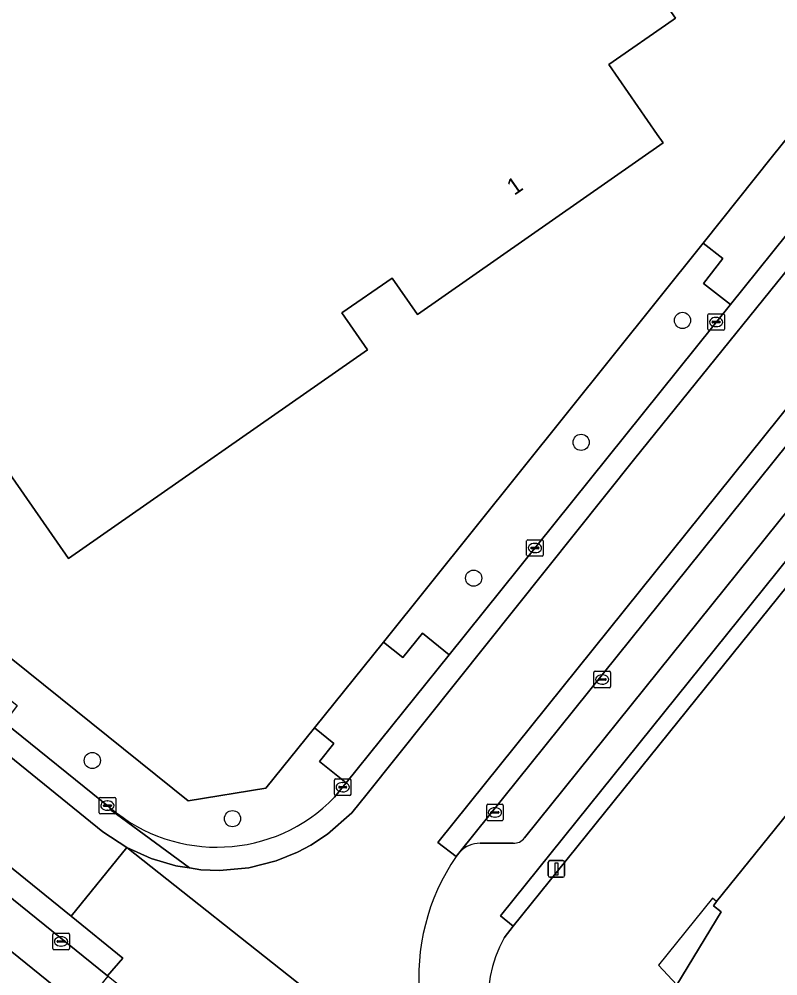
# Model space of a CAD drawing. Extents: x 156702 to 158052, y 387630 to 388992.
# Drawn here: x 157335.4 to 157381.2, y 388068.3 to 388126 of the extents above; entities that cross this region are included whole.
import ezdxf

# ---------------------------------------------------------------- set-up
doc = ezdxf.new("R2010")
doc.units = 0
for name, color, linetype in [('IMGEO_Berm_groen', 7, 'Continuous'), ('IMGEO_Boom', 7, 'Continuous'), ('IMGEO_Erf', 7, 'Continuous'), ('IMGEO_Groenvoorziening', 7, 'Continuous'), ('IMGEO_Hek', 7, 'Continuous'), ('IMGEO_Kolk', 7, 'Continuous'), ('IMGEO_Lichtmast', 7, 'Continuous'), ('IMGEO_Pand', 7, 'Continuous'), ('IMGEO_Pand_nummerreeks', 7, 'Continuous'), ('IMGEO_Pand_overbouw', 7, 'Continuous'), ('IMGEO_Parkeervlak_open', 7, 'Continuous'), ('IMGEO_Rijbaan_lokaal_gesloten', 7, 'Continuous'), ('IMGEO_Rijbaan_lokaal_open', 7, 'Continuous'), ('IMGEO_Voetpad_open', 7, 'Continuous')]:
    doc.layers.add(name, color=color, linetype=linetype)

msp = doc.modelspace()

# ---------------------------------------------------------------- linework, layer by layer
at = {"layer": 'IMGEO_Berm_groen'}
msp.add_lwpolyline([(157378.344, 388108.801), (157376.726, 388110.062), (157377.891, 388111.57), (157376.693, 388112.497), (157357.392, 388088.42), (157358.573, 388087.49), (157359.755, 388088.963), (157361.36, 388087.666)], close=True, dxfattribs=at)
for points in [[(157354.447, 388079.064), (157355.149, 388079.934), (157353.539, 388081.22), (157354.397, 388082.311), (157353.239, 388083.252), (157350.282, 388079.607), (157345.604, 388078.857), (157309.704, 388107.668)], [(157316.025, 388098.512), (157328.627, 388088.335), (157329.374, 388089.304), (157335.28, 388084.592), (157334.514, 388083.582), (157340.899, 388078.426)]]:
    msp.add_lwpolyline(points, dxfattribs=at)
msp.add_arc((157347.333, 388085.955), 9.904, 229.48202, 315.91032, dxfattribs=at)
at = {"layer": 'IMGEO_Boom'}
for centre in [(157375.454, 388107.837), (157369.333, 388100.48), (157362.84, 388092.285), (157339.812, 388081.28), (157348.276, 388077.77)]:
    msp.add_circle(centre, 0.489, dxfattribs=at)
at = {"layer": 'IMGEO_Erf'}
for points in [[(157304.594, 388111.931), (157309.704, 388107.668), (157345.604, 388078.857), (157350.282, 388079.607), (157353.239, 388083.252), (157357.392, 388088.42), (157376.693, 388112.497), (157380.893, 388117.749), (157391.144, 388130.462), (157404.098, 388146.633), (157406.558, 388149.7), (157418.329, 388164.322), (157428.032, 388175.523), (157430.343, 388177.94), (157441.633, 388189.119), (157442.935, 388190.379), (157453.889, 388200.705), (157463.105, 388209.35), (157478.926, 388224.264), (157484.402, 388229.388), (157504.128, 388247.959), (157518.512, 388268.247), (157504.449, 388292.394)], [(157493.249, 388214.823), (157491.107, 388212.731), (157491.239, 388212.61), (157490.267, 388211.711), (157481.015, 388202.978), (157480.83, 388203.161), (157468.85, 388191.959), (157469.027, 388191.734), (157464.53, 388187.517), (157456.336, 388179.654), (157444.998, 388168.465), (157439.451, 388162.839), (157439.425, 388162.812), (157437.029, 388160.17), (157418.031, 388136.851), (157411.021, 388128.098), (157365.224, 388071.291), (157364.694, 388070.576)], [(157375.12, 388067.746), (157377.791, 388072.155), (157377.317, 388072.514), (157377.518, 388072.763), (157393.215, 388092.187), (157408.126, 388110.639), (157409.261, 388112.047), (157409.462, 388112.296), (157409.944, 388111.907), (157413.497, 388115.283), (157415.217, 388117.029), (157415.445, 388117.256), (157419.983, 388112.463), (157419.758, 388112.25), (157419.62, 388112.395), (157417.986, 388110.394), (157419.843, 388108.498), (157420.585, 388107.61), (157424.453, 388103.559), (157425.389, 388102.574), (157427.433, 388104.491), (157431.942, 388099.714), (157436.485, 388094.9)]]:
    msp.add_lwpolyline(points, dxfattribs=at)
msp.add_lwpolyline([(157351.143, 388160.273), (157367.369, 388137.046), (157375.029, 388126.081), (157374.884, 388125.98), (157371, 388123.278), (157373.931, 388119.066), (157374.291, 388118.549), (157359.447, 388108.199), (157357.92, 388110.389), (157354.876, 388108.287), (157356.429, 388106.057), (157338.379, 388093.469), (157327.058, 388109.73), (157327.201, 388109.843), (157311.351, 388132.544), (157338.607, 388151.537)], close=True, dxfattribs=at)
msp.add_arc((157370.722, 388067.056), 6.981, 149.71613, 230.3307, dxfattribs=at)
at = {"layer": 'IMGEO_Groenvoorziening'}
msp.add_lwpolyline([(157365.224, 388071.291), (157411.021, 388128.098), (157410.172, 388128.763), (157409.295, 388127.628), (157364.459, 388071.912)], close=True, dxfattribs=at)
at = {"layer": 'IMGEO_Hek'}
for points in [[(157380.893, 388117.749), (157376.693, 388112.497)], [(157376.693, 388112.497), (157357.392, 388088.42)], [(157304.594, 388111.931), (157309.704, 388107.668), (157345.604, 388078.857), (157350.282, 388079.607), (157353.239, 388083.252)]]:
    msp.add_lwpolyline(points, dxfattribs=at)
at = {"layer": 'IMGEO_Kolk'}
for p, q in [((157376.983, 388107.315), (157376.983, 388108.167)), ((157377.058, 388108.241), (157377.91, 388108.241)), ((157377.984, 388108.167), (157377.984, 388107.315)), ((157377.242, 388107.735), (157377.242, 388107.747)), ((157377.68, 388107.698), (157377.282, 388107.698)), ((157377.285, 388107.784), (157377.683, 388107.784)), ((157377.471, 388108.021), (157377.496, 388108.021)), ((157377.726, 388107.747), (157377.726, 388107.735)), ((157377.91, 388107.241), (157377.058, 388107.241)), ((157377.494, 388107.461), (157377.469, 388107.461)), ((157366.043, 388093.679), (157366.043, 388094.531)), ((157366.118, 388094.605), (157366.97, 388094.605)), ((157366.531, 388094.385), (157366.556, 388094.385)), ((157367.044, 388094.531), (157367.044, 388093.679)), ((157366.302, 388094.099), (157366.302, 388094.111)), ((157366.74, 388094.062), (157366.342, 388094.062)), ((157366.345, 388094.148), (157366.743, 388094.148)), ((157366.554, 388093.825), (157366.529, 388093.825)), ((157366.786, 388094.111), (157366.786, 388094.099)), ((157366.97, 388093.605), (157366.118, 388093.605)), ((157370.101, 388085.741), (157370.101, 388086.593)), ((157370.176, 388086.667), (157371.028, 388086.667)), ((157370.589, 388086.447), (157370.614, 388086.447)), ((157371.102, 388086.593), (157371.102, 388085.741)), ((157371.028, 388085.667), (157370.176, 388085.667)), ((157370.36, 388086.161), (157370.36, 388086.173)), ((157370.798, 388086.124), (157370.4, 388086.124)), ((157370.403, 388086.21), (157370.801, 388086.21)), ((157370.612, 388085.887), (157370.587, 388085.887)), ((157370.844, 388086.173), (157370.844, 388086.161)), ((157354.433, 388079.245), (157354.433, 388080.097)), ((157354.508, 388080.171), (157355.36, 388080.171)), ((157354.921, 388079.951), (157354.946, 388079.951)), ((157355.434, 388080.097), (157355.434, 388079.245)), ((157354.692, 388079.665), (157354.692, 388079.677)), ((157355.13, 388079.628), (157354.732, 388079.628)), ((157354.735, 388079.714), (157355.133, 388079.714)), ((157354.944, 388079.391), (157354.919, 388079.391)), ((157355.176, 388079.677), (157355.176, 388079.665)), ((157340.223, 388078.132), (157340.223, 388078.984)), ((157340.298, 388079.058), (157341.15, 388079.058)), ((157340.711, 388078.838), (157340.736, 388078.838)), ((157341.224, 388078.984), (157341.224, 388078.132)), ((157355.36, 388079.171), (157354.508, 388079.171)), ((157340.482, 388078.552), (157340.482, 388078.564)), ((157340.92, 388078.515), (157340.522, 388078.515)), ((157340.525, 388078.601), (157340.923, 388078.601)), ((157340.734, 388078.278), (157340.709, 388078.278)), ((157340.966, 388078.564), (157340.966, 388078.552)), ((157363.628, 388077.723), (157363.628, 388078.575)), ((157363.703, 388078.649), (157364.555, 388078.649)), ((157363.887, 388078.143), (157363.887, 388078.155)), ((157363.93, 388078.192), (157364.328, 388078.192)), ((157364.116, 388078.429), (157364.141, 388078.429)), ((157364.371, 388078.155), (157364.371, 388078.143)), ((157364.629, 388078.575), (157364.629, 388077.723)), ((157341.15, 388078.058), (157340.298, 388078.058)), ((157364.555, 388077.649), (157363.703, 388077.649)), ((157364.325, 388078.106), (157363.927, 388078.106)), ((157364.139, 388077.869), (157364.114, 388077.869)), ((157337.424, 388069.939), (157337.424, 388070.791)), ((157337.499, 388070.865), (157338.351, 388070.865)), ((157337.912, 388070.645), (157337.937, 388070.645)), ((157338.425, 388070.791), (157338.425, 388069.939)), ((157337.683, 388070.359), (157337.683, 388070.371)), ((157338.121, 388070.322), (157337.723, 388070.322)), ((157337.726, 388070.408), (157338.124, 388070.408)), ((157337.935, 388070.085), (157337.91, 388070.085)), ((157338.167, 388070.371), (157338.167, 388070.359)), ((157338.351, 388069.865), (157337.499, 388069.865))]:
    msp.add_line(p, q, dxfattribs=at)
for points in [[(157376.983, 388107.315), (157376.983, 388108.167)], [(157377.058, 388108.241), (157377.91, 388108.241)], [(157377.984, 388108.167), (157377.984, 388107.315)], [(157377.91, 388107.241), (157377.058, 388107.241)], [(157366.043, 388093.679), (157366.043, 388094.531)], [(157366.118, 388094.605), (157366.97, 388094.605)], [(157367.044, 388094.531), (157367.044, 388093.679)], [(157366.97, 388093.605), (157366.118, 388093.605)], [(157370.101, 388085.741), (157370.101, 388086.593)], [(157370.176, 388086.667), (157371.028, 388086.667)], [(157371.102, 388086.593), (157371.102, 388085.741)], [(157371.028, 388085.667), (157370.176, 388085.667)], [(157354.433, 388079.245), (157354.433, 388080.097)], [(157354.508, 388080.171), (157355.36, 388080.171)], [(157355.434, 388080.097), (157355.434, 388079.245)], [(157340.223, 388078.132), (157340.223, 388078.984)], [(157340.298, 388079.058), (157341.15, 388079.058)], [(157341.224, 388078.984), (157341.224, 388078.132)], [(157355.36, 388079.171), (157354.508, 388079.171)], [(157363.628, 388077.723), (157363.628, 388078.575)], [(157363.703, 388078.649), (157364.555, 388078.649)], [(157364.629, 388078.575), (157364.629, 388077.723)], [(157341.15, 388078.058), (157340.298, 388078.058)], [(157364.555, 388077.649), (157363.703, 388077.649)], [(157337.424, 388069.939), (157337.424, 388070.791)], [(157337.499, 388070.865), (157338.351, 388070.865)], [(157338.425, 388070.791), (157338.425, 388069.939)], [(157338.351, 388069.865), (157337.499, 388069.865)]]:
    msp.add_lwpolyline(points, dxfattribs=at)
for centre, radius, start, end in [((157377.06, 388108.165), 0.0765, 91.55205, 178.44795), ((157377.06, 388108.165), 0.0765, 91.55205, 178.44795), ((157377.908, 388108.165), 0.0765, 1.55205, 88.44795), ((157377.908, 388108.165), 0.0765, 1.55205, 88.44795), ((157377.282, 388107.744), 0.0403, 85.87752, 175.75265), ((157377.279, 388107.734), 0.0366, 178.93798, 274.71019), ((157377.683, 388107.741), 0.043, 264.86636, 352.45326), ((157377.687, 388107.746), 0.0386, 1.73085, 96.63898), ((157377.06, 388107.317), 0.0765, 181.55205, 268.44795), ((157377.06, 388107.317), 0.0765, 181.55205, 268.44795), ((157377.908, 388107.317), 0.0765, 271.55205, 358.44795), ((157377.908, 388107.317), 0.0765, 271.55205, 358.44795), ((157366.12, 388094.529), 0.0765, 91.55205, 178.44795), ((157366.12, 388094.529), 0.0765, 91.55205, 178.44795), ((157366.968, 388094.529), 0.0765, 1.55205, 88.44795), ((157366.968, 388094.529), 0.0765, 1.55205, 88.44795), ((157366.342, 388094.108), 0.0403, 85.87752, 175.75265), ((157366.339, 388094.098), 0.0366, 178.93798, 274.71019), ((157366.743, 388094.105), 0.043, 264.86636, 352.45326), ((157366.747, 388094.11), 0.0386, 1.73085, 96.63898), ((157366.12, 388093.681), 0.0765, 181.55205, 268.44795), ((157366.12, 388093.681), 0.0765, 181.55205, 268.44795), ((157366.968, 388093.681), 0.0765, 271.55205, 358.44795), ((157366.968, 388093.681), 0.0765, 271.55205, 358.44795), ((157370.178, 388086.591), 0.0765, 91.55205, 178.44795), ((157370.178, 388086.591), 0.0765, 91.55205, 178.44795), ((157371.026, 388086.591), 0.0765, 1.55205, 88.44795), ((157371.026, 388086.591), 0.0765, 1.55205, 88.44795), ((157370.178, 388085.743), 0.0765, 181.55205, 268.44795), ((157370.178, 388085.743), 0.0765, 181.55205, 268.44795), ((157370.4, 388086.17), 0.0403, 85.87752, 175.75265), ((157370.397, 388086.16), 0.0366, 178.93798, 274.71019), ((157370.801, 388086.167), 0.043, 264.86636, 352.45326), ((157370.805, 388086.172), 0.0386, 1.73085, 96.63898), ((157371.026, 388085.743), 0.0765, 271.55205, 358.44795), ((157371.026, 388085.743), 0.0765, 271.55205, 358.44795), ((157354.51, 388080.095), 0.0765, 91.55205, 178.44795), ((157354.51, 388080.095), 0.0765, 91.55205, 178.44795), ((157355.358, 388080.095), 0.0765, 1.55205, 88.44795), ((157355.358, 388080.095), 0.0765, 1.55205, 88.44795), ((157354.732, 388079.674), 0.0403, 85.87752, 175.75265), ((157354.729, 388079.664), 0.0366, 178.93798, 274.71019), ((157355.133, 388079.671), 0.043, 264.86636, 352.45326), ((157355.137, 388079.676), 0.0386, 1.73085, 96.63898), ((157340.3, 388078.982), 0.0765, 91.55205, 178.44795), ((157340.3, 388078.982), 0.0765, 91.55205, 178.44795), ((157341.148, 388078.982), 0.0765, 1.55205, 88.44795), ((157341.148, 388078.982), 0.0765, 1.55205, 88.44795), ((157354.51, 388079.247), 0.0765, 181.55205, 268.44795), ((157354.51, 388079.247), 0.0765, 181.55205, 268.44795), ((157355.358, 388079.247), 0.0765, 271.55205, 358.44795), ((157355.358, 388079.247), 0.0765, 271.55205, 358.44795), ((157340.522, 388078.561), 0.0403, 85.87752, 175.75265), ((157340.519, 388078.551), 0.0366, 178.93798, 274.71019), ((157340.923, 388078.558), 0.043, 264.86636, 352.45326), ((157340.927, 388078.563), 0.0386, 1.73085, 96.63898), ((157363.705, 388078.573), 0.0765, 91.55205, 178.44795), ((157363.705, 388078.573), 0.0765, 91.55205, 178.44795), ((157363.927, 388078.152), 0.0403, 85.87752, 175.75265), ((157364.332, 388078.154), 0.0386, 1.73085, 96.63898), ((157364.553, 388078.573), 0.0765, 1.55205, 88.44795), ((157364.553, 388078.573), 0.0765, 1.55205, 88.44795), ((157340.3, 388078.134), 0.0765, 181.55205, 268.44795), ((157340.3, 388078.134), 0.0765, 181.55205, 268.44795), ((157341.148, 388078.134), 0.0765, 271.55205, 358.44795), ((157341.148, 388078.134), 0.0765, 271.55205, 358.44795), ((157363.705, 388077.725), 0.0765, 181.55205, 268.44795), ((157363.705, 388077.725), 0.0765, 181.55205, 268.44795), ((157363.924, 388078.142), 0.0366, 178.93798, 274.71019), ((157364.328, 388078.149), 0.043, 264.86636, 352.45326), ((157364.553, 388077.725), 0.0765, 271.55205, 358.44795), ((157364.553, 388077.725), 0.0765, 271.55205, 358.44795), ((157337.501, 388070.789), 0.0765, 91.55205, 178.44795), ((157337.501, 388070.789), 0.0765, 91.55205, 178.44795), ((157338.349, 388070.789), 0.0765, 1.55205, 88.44795), ((157338.349, 388070.789), 0.0765, 1.55205, 88.44795), ((157337.723, 388070.368), 0.0403, 85.87752, 175.75265), ((157337.72, 388070.358), 0.0366, 178.93798, 274.71019), ((157338.124, 388070.365), 0.043, 264.86636, 352.45326), ((157338.128, 388070.37), 0.0386, 1.73085, 96.63898), ((157337.501, 388069.941), 0.0765, 181.55205, 268.44795), ((157337.501, 388069.941), 0.0765, 181.55205, 268.44795), ((157338.349, 388069.941), 0.0765, 271.55205, 358.44795), ((157338.349, 388069.941), 0.0765, 271.55205, 358.44795)]:
    msp.add_arc(centre, radius, start, end, dxfattribs=at)
for centre, major_axis, ratio, start_param, end_param in [((157377.47, 388107.741), (-0.387, 0.002), 0.722429, 4.712389, 7.853982), ((157377.495, 388107.741), (-0.39, 0.002), 0.717154, 1.570796, 4.712389), ((157366.53, 388094.105), (-0.387, 0.002), 0.722429, 4.712389, 7.853982), ((157366.555, 388094.105), (-0.39, 0.002), 0.717154, 1.570796, 4.712389), ((157370.588, 388086.167), (-0.387, 0.002), 0.722429, 4.712389, 7.853982), ((157370.613, 388086.167), (-0.39, 0.002), 0.717154, 1.570796, 4.712389), ((157354.92, 388079.671), (-0.387, 0.002), 0.722429, 4.712389, 7.853982), ((157354.945, 388079.671), (-0.39, 0.002), 0.717154, 1.570796, 4.712389), ((157340.71, 388078.558), (-0.387, 0.002), 0.722429, 4.712389, 7.853982), ((157340.735, 388078.558), (-0.39, 0.002), 0.717154, 1.570796, 4.712389), ((157364.115, 388078.149), (-0.387, 0.002), 0.722429, 4.712389, 7.853982), ((157364.14, 388078.149), (-0.39, 0.002), 0.717154, 1.570796, 4.712389), ((157337.911, 388070.365), (-0.387, 0.002), 0.722429, 4.712389, 7.853982), ((157337.936, 388070.365), (-0.39, 0.002), 0.717154, 1.570796, 4.712389)]:
    msp.add_ellipse(centre, major_axis=major_axis, ratio=ratio, start_param=start_param, end_param=end_param, dxfattribs=at)
at = {"layer": 'IMGEO_Lichtmast'}
for p, q in [((157367.346, 388074.338), (157367.346, 388075.138)), ((157367.346, 388075.138), (157367.346, 388074.338)), ((157367.446, 388075.238), (157368.236, 388075.238)), ((157368.236, 388075.238), (157367.446, 388075.238)), ((157368.336, 388075.138), (157368.336, 388074.338)), ((157368.336, 388074.338), (157368.336, 388075.138)), ((157368.236, 388074.238), (157367.446, 388074.238)), ((157367.446, 388074.238), (157368.236, 388074.238))]:
    msp.add_line(p, q, dxfattribs=at)
msp.add_lwpolyline([(157367.766, 388075.113), (157367.916, 388075.113), (157367.916, 388074.363), (157367.766, 388074.363), (157367.766, 388075.113)], dxfattribs=at)
for centre, start, end in [((157367.446, 388075.138), 90, 180), ((157367.446, 388075.138), 90, 180), ((157368.236, 388075.138), 0, 90), ((157368.236, 388075.138), 360, 90), ((157367.446, 388074.338), 180, 270), ((157367.446, 388074.338), 180, 270), ((157368.236, 388074.338), 270, 0), ((157368.236, 388074.338), 270, 0)]:
    msp.add_arc(centre, 0.1, start, end, dxfattribs=at)
at = {"layer": 'IMGEO_Pand'}
for points in [[(157371, 388123.278), (157374.884, 388125.98), (157375.029, 388126.081), (157367.369, 388137.046), (157351.143, 388160.273), (157338.607, 388151.537), (157311.351, 388132.544), (157327.201, 388109.843), (157327.058, 388109.73), (157338.379, 388093.469), (157356.429, 388106.057), (157354.876, 388108.287), (157357.92, 388110.389), (157359.447, 388108.199), (157374.291, 388118.549), (157373.931, 388119.066)], [(157401.351, 388085.55), (157393.215, 388092.187), (157377.518, 388072.763), (157377.317, 388072.514), (157377.791, 388072.155), (157375.12, 388067.746), (157373.801, 388065.569), (157373.516, 388065.423), (157378.044, 388060.636), (157378.275, 388060.85), (157378.097, 388061.046), (157379.662, 388063.087), (157381.537, 388061.074), (157399.778, 388083.607), (157400.684, 388084.726)]]:
    msp.add_lwpolyline(points, close=True, dxfattribs=at)
at = {"layer": 'IMGEO_Pand_overbouw'}
msp.add_lwpolyline([(157377.518, 388072.763), (157377.272, 388072.972), (157374.006, 388068.927), (157375.12, 388067.746), (157377.791, 388072.155), (157377.317, 388072.514)], close=True, dxfattribs=at)
at = {"layer": 'IMGEO_Parkeervlak_open'}
for points in [[(157407.869, 388128.768), (157405.894, 388130.347), (157362.018, 388075.78)], [(157365.917, 388076.612), (157407.869, 388128.768)], [(157363.228, 388076.287), (157365.218, 388076.297)]]:
    msp.add_lwpolyline(points, dxfattribs=at)
for centre, radius, start, end in [((157365.291, 388077.069), 0.775, 264.63114, 323.88569), ((157363.235, 388074.573), 1.714, 90.23714, 135.23103)]:
    msp.add_arc(centre, radius, start, end, dxfattribs=at)
at = {"layer": 'IMGEO_Rijbaan_lokaal_gesloten'}
for points in [[(157159.256, 388297.816), (157160.307, 388298.772), (157166.301, 388290.299), (157236.347, 388190.018), (157288.771, 388114.767), (157287.657, 388113.917), (157306.474, 388095.88), (157307.404, 388097.063), (157338.534, 388071.878), (157341.899, 388076.038), (157340.456, 388076.982), (157309.901, 388101.717)], [(157372.577, 388099.512), (157397.82, 388130.747), (157409.349, 388145.114), (157418.054, 388155.99), (157428.31, 388168.424), (157433.998, 388174.762), (157442.081, 388182.987), (157451.011, 388191.483), (157458.709, 388198.857), (157466.448, 388206.061), (157472.586, 388211.776), (157482.524, 388221.195), (157508.983, 388245.953), (157519.658, 388255.905)], [(157441.766, 388173.495), (157445.382, 388177.09), (157464.923, 388195.684), (157464.997, 388195.754), (157486.423, 388215.896), (157487.488, 388216.939), (157486.56, 388217.944), (157464.339, 388197.057), (157445.628, 388179.257), (157440.454, 388174.149), (157437.14, 388170.615), (157432.703, 388165.68), (157427.336, 388159.248), (157360.67, 388076.338), (157361.788, 388075.495), (157362.018, 388075.78), (157405.894, 388130.347)], [(157361.788, 388075.495), (157360.67, 388076.338), (157427.336, 388159.248), (157432.703, 388165.68), (157437.14, 388170.615), (157440.454, 388174.149), (157445.628, 388179.257), (157464.339, 388197.057), (157486.56, 388217.944)], [(157425.667, 388167.547), (157419.954, 388160.554), (157409.376, 388147.415), (157406.909, 388144.334), (157395.189, 388129.737), (157378.344, 388108.801), (157361.36, 388087.666), (157355.149, 388079.934), (157354.447, 388079.064)], [(157397.82, 388130.747), (157372.577, 388099.512), (157356.41, 388079.268), (157355.48, 388078.115), (157354.015, 388076.833), (157353.016, 388076.181), (157352.205, 388075.752), (157350.909, 388075.228), (157349.26, 388074.812), (157347.485, 388074.649), (157346.364, 388074.69), (157345.672, 388074.796), (157344.981, 388074.902), (157344.863, 388074.92), (157343.374, 388075.363), (157341.899, 388076.038), (157363.348, 388059.054)], [(157284.128, 388130.537), (157290.068, 388122.059), (157292.715, 388118.524), (157292.839, 388118.359), (157297.417, 388113.326), (157302.391, 388108.413), (157309.901, 388101.717), (157340.456, 388076.982), (157341.899, 388076.038), (157343.374, 388075.363), (157344.863, 388074.92), (157344.981, 388074.902), (157345.672, 388074.796), (157340.891, 388078.329), (157340.899, 388078.426), (157334.514, 388083.582), (157328.627, 388088.335), (157316.025, 388098.512)], [(157340.899, 388078.426), (157340.891, 388078.329), (157345.672, 388074.796), (157346.364, 388074.69), (157347.485, 388074.649), (157349.26, 388074.812), (157350.909, 388075.228), (157352.205, 388075.752), (157353.016, 388076.181), (157354.015, 388076.833), (157355.48, 388078.115), (157356.41, 388079.268), (157372.577, 388099.512)], [(157307.076, 388095.433), (157322.115, 388083.308), (157340.735, 388068.296), (157341.664, 388069.346), (157338.534, 388071.878), (157307.404, 388097.063)], [(157341.899, 388076.038), (157338.534, 388071.878), (157341.664, 388069.346), (157340.735, 388068.296), (157340.763, 388068.274), (157359.484, 388053.181)], [(157367.559, 388055.453), (157363.705, 388058.742), (157363.348, 388059.054), (157341.899, 388076.038)]]:
    msp.add_lwpolyline(points, dxfattribs=at)
for centre, radius, start, end in [((157347.333, 388085.955), 9.904, 229.48202, 315.91032), ((157372.416, 388068.209), 12.886, 145.56856, 225.27198)]:
    msp.add_arc(centre, radius, start, end, dxfattribs=at)
at = {"layer": 'IMGEO_Rijbaan_lokaal_open'}
for points in [[(157376.693, 388112.497), (157377.891, 388111.57), (157376.726, 388110.062), (157378.344, 388108.801), (157395.189, 388129.737), (157393.555, 388130.997), (157392.39, 388129.493), (157391.144, 388130.462), (157380.893, 388117.749)], [(157353.239, 388083.252), (157354.397, 388082.311), (157353.539, 388081.22), (157355.149, 388079.934), (157361.36, 388087.666), (157359.755, 388088.963), (157358.573, 388087.49), (157357.392, 388088.42)]]:
    msp.add_lwpolyline(points, close=True, dxfattribs=at)
at = {"layer": 'IMGEO_Voetpad_open'}
for points in [[(157364.694, 388070.576), (157365.224, 388071.291), (157364.459, 388071.912), (157409.295, 388127.628), (157407.869, 388128.768), (157365.917, 388076.612)], [(157365.218, 388076.297), (157363.228, 388076.287)], [(157362.018, 388075.78), (157361.788, 388075.495)]]:
    msp.add_lwpolyline(points, dxfattribs=at)
for points in [[(157322.115, 388083.308), (157320.551, 388081.367), (157339.186, 388066.318), (157340.763, 388068.274), (157340.735, 388068.296)], [(157320.551, 388081.367), (157320.382, 388081.503), (157319.233, 388080.076), (157320.37, 388079.154), (157319.509, 388078.127), (157328.331, 388071.037), (157335.501, 388065.276), (157336.327, 388066.305), (157338.064, 388064.911), (157339.186, 388066.318)]]:
    msp.add_lwpolyline(points, close=True, dxfattribs=at)
for centre, radius, start, end in [((157365.291, 388077.069), 0.775, 264.63114, 323.88569), ((157363.235, 388074.573), 1.714, 90.23714, 135.23103), ((157372.416, 388068.209), 12.886, 145.56856, 225.27198), ((157370.722, 388067.056), 6.981, 149.71613, 230.3307)]:
    msp.add_arc(centre, radius, start, end, dxfattribs=at)

# ---------------------------------------------------------------- texts
at = {"layer": 'IMGEO_Pand_nummerreeks'}
msp.add_text('1', height=1, rotation=34.88619, dxfattribs=at).set_placement((157365.295, 388115.349))

doc.saveas('drawing.dxf')
